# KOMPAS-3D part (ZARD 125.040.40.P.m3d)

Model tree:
1. Булева операция:21
2. Булева операция:22
3. Булева операция:23
4. Булева операция:24
5. Булева операция:25
6. Булева операция:26
7. Булева операция:27
8. Булева операция:28
9. Булева операция:29
10. Булева операция:30
11. Булева операция:31
12. Булева операция:32
13. Булева операция:33
14. Булева операция:34
15. Булева операция:35
